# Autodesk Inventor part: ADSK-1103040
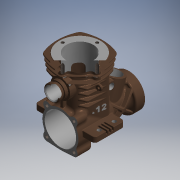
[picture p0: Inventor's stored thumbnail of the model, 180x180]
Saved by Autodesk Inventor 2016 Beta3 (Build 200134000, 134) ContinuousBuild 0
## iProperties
Shininess: 11.0
Compacted: True
Length Units: 11269
Angle Units: 11279
Time Units: 11290
Mass Units: 11286
Length Display Precision: 2
Angle Display Precision: 2
Created: 2000-07
Part Number: ADSK-1103040
Document SubType Name: Modeling
Description: ENGINE  CASE - REAR
Mass: 106.427 g
Surface Area: 158.116 cm^2
Volume: 13.1716 cm^3
Density: 8.08 g/cm^3
Material: Stainless Steel
Appearance: Bronze - Satin
Density: 0.0
Volumn: 0.0
Area: 0.0
PropertySet Name: Model Information
Control State: 0
Master: False
Checked Out: False
Author: Autodesk, Inc.
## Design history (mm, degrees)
node "Extrusion1" dims "d2" = 3.5, "d3" = 0
  sketch "Sketch2"
    geometry: L1 (-28.715, -16.977)-(11.285, -16.977); L2 (11.285, -16.977)-(11.285, 3.023); L3 (11.285, 3.023)-(-28.715, 3.023); L4 (-28.715, 3.023)-(-28.715, -16.977)
    constraints: 8 end point, 2 parallel, 1 horizontal, 1 perpendicular
    dimensions: "d0" = 40 distance of L2.end L3.end; "d1" = 20 distance of L3.end L1.start
workplane "Work Plane1"
workplane "Work Plane2"
node "Extrusion2" dims "d6" = 25.5, "d7" = 0
  sketch "Sketch3"
    geometry: L1 (20, -16.8)-(20, 16.8) reference; L2 (0, 0)-(40, 0) reference; C1 r 12 at (20, 0)
    constraints: 1 centre point, 1 midpoint
    dimensions: "d5" = 24 diameter of C1
node "Extrusion3" dims "d13" = 25, "d14" = 0
  sketch "Sketch4"
    geometry: L1 (-20.715, 3.023)-(3.285, 3.023); L2 (-2.715, -16.977)-(-14.715, -16.977); L3 (-8.715, -21.506)-(-8.715, 7.111) reference; L4 (-28.715, -16.977)-(-20.715, -16.977) reference; A1 r 36.333 centre (-33.049, 3.023) between (-2.715, -16.977) and (3.285, 3.023); A2 r 36.333 centre (15.618, 3.023) between (-20.715, 3.023) and (-14.715, -16.977)
    constraints: 4 end point, 4 point on circle, 2 centre point, 2 point on line, 1 collinear, 1 horizontal
    dimensions: "d8" = 24 distance of L1.start L1.end; "d9" = 12 distance of L2.start L2.end; "d10" = 6 distance from line of L3 L2.start (= 0.5 x d9); "d11" = 12 distance from line of L1.end L3 (= 0.5 x d8); "d12" = 20 distance between parallel lines of L2 L1
node "Extrusion5" dims "d18" = 14, "d19" = 0
  sketch "Sketch6"
    geometry: C1 r 11.33 at (0, 0); C2 r 8 at (0, 0); C3 r 12 at (0, 0) reference
    constraints: 2 centre point, 1 coincident
    dimensions: "d17" = 16 diameter of C2
workplane "Work Plane15"
node "Extrusion6" dims "d21" = 6, "d22" = 0
  sketch "Sketch7"
    geometry: C1 r 7.5 at (0, 0); C2 r 11 at (0, 0)
    constraints: 2 centre point, 1 coincident
    dimensions: "d20" = 22 diameter of C2
fillet "Fillet48" dims "d248" = 2
fillet "Fillet53" dims "d264" = 2, "d265" = 1
feature "LoftSrf2" dims "d266" = 0, "d267" = 90 deg, "d268" = 0, "d269" = 90 deg
  node "Edges3"
  node "Edges4"
feature "OffsetSrf1" dims "d270" = 1, "d271" = 1
node "Revolution1" dims "d28" = 90 deg
  sketch "Sketch10"
    geometry: L1 (-20, -3.5)-(0, -3.5) reference; L2 (-20.351, 1.344)-(-25.14, 14.5); L3 (-25.14, 14.5)-(-31.718, 12.106); L4 (-31.718, 12.106)-(-26.929, -1.05); L5 (-26.929, -1.05)-(-20.351, 1.344); L6 (-22.5, 4.5)-(-36.5, 4.5) reference; L7 (-22.5, -15.5)-(-22.5, 8.5) reference; 1 further point
    constraints: 8 end point, 2 perpendicular, 2 point on line, 1 parallel
    dimensions: "d26" = 70 deg angle of L1 L2; "d27" = 14 diameter of L2 L4; "d231" = 14 distance of L2.start L2.end; "d241" = 10 distance from line of L6 L2.end; "d242" = 1 distance from line of L7 point (-21.5, 4.5)
workplane "Work Plane3"
  workaxis "Work Axis1"
workaxis "Work Axis2"
workplane "Work Plane5"
workplane "Work Plane30"
node "Extrusion12" dims "d54" = 8, "d55" = 0
  sketch "Sketch15"
    geometry: L1 (-9, 9)-(9, 9); L2 (9, 9)-(9, -9); L3 (9, -9)-(-9, -9); L4 (-9, -9)-(-9, 9); C1 r 12 at (0, 0) reference; C2 r 2.5 at (-9, 9); C3 r 2.5 at (9, 9); C4 r 2.5 at (9, -9); C5 r 2.5 at (-9, -9)
    constraints: 8 end point, 4 centre point, 4 coincident, 3 equal radius, 2 parallel, 2 perpendicular, 1 horizontal
    dimensions: "d50" = 18 distance of L2.end L3.end; "d51" = 9 distance from line of C1.centre L4 (= 0.5 x d50); "d52" = 9 distance from line of C1.centre L3 (= d51); "d53" = 5 diameter of C3
node "Extrusion13" dims "d56" = 8, "d57" = 0
  sketch "Sketch16"
    geometry: L1 (10.857, -11.496)-(19.314, -11.98); L2 (29.143, -11.496)-(20.686, -11.98); A1 r 2.5 centre (11, -9) between (10.039, -6.692) and (13.308, -9.961) reference; A2 r 12 centre (20, 0) between (13.308, -9.961) and (26.692, -9.961) reference; A3 r 2.5 centre (29, -9) between (26.692, -9.961) and (29.961, -6.692) reference
    constraints: 4 end point, 4 point on circle, 4 tangent
node "Fillet1" dims "d58" = 2.5
node "Fillet3" dims "d60" = 5
node "Fillet4" dims "d61" = 3
node "Fillet5" dims "d62" = 2
node "Revolution2" dims "d63" = 180 deg
  sketch "Sketch17"
    geometry: L1 (0.686, 11.98)-(9.143, 11.496) reference; L2 (9.143, 11.496)-(0.686, 11.98); L3 (0.686, 11.98)-(0.543, 9.484); L4 (0.543, 9.484)-(9, 9); L5 (9, 9)-(9.143, 11.496); L6 (9, 9)-(11.496, 8.857); A1 r 12 centre (0, 0) between (9.961, 6.692) and (0.686, 11.98) reference; A2 r 2.5 centre (9, 9) between (9.961, 6.692) and (9.143, 11.496) reference
    constraints: 10 end point, 3 equal length, 2 perpendicular, 2 tangent, 1 point on circle, 1 point on line
node "Mirror2"
node "Fillet6" dims "d64" = 2.5
node "Fillet8" dims "d66" = 3.5
node "Fillet17" dims "d75" = 2
node "Fillet18" dims "d76" = 0.3
node "Fillet19" dims "d77" = 0.5
node "Extrusion14" dims "d84" = 9, "d85" = 0
  sketch "Sketch18"
    geometry: L1 (-17.028, 3.023)-(-0.402, 3.023) reference; L2 (-8.715, -25.077)-(-8.715, 10.623) reference; C1 r 10.018 at (-8.715, -6.996); A1 r 36.333 centre (15.618, 3.023) between (-20.508, -0.85) and (-16.281, -14.371) reference
    constraints: 2 tangent, 1 centre point, 1 point on line
node "Extrusion15" dims "d90" = 1, "d91" = 0
  sketch "Sketch19"
    geometry: L1 (5.035, 6.754)-(-22.465, 6.754); L2 (-22.465, 6.754)-(-22.465, -20.746); L3 (-22.465, -20.746)-(5.035, -20.746); L4 (5.035, -20.746)-(5.035, 6.754); A1 r 10.018 centre (-8.715, -6.996) between (0.549, -10.81) and (-8.715, 3.023) reference; A2 r 27.5 centre (-22.465, -6.996) between (2.599, -18.31) and (2.599, 4.319); A3 r 27.5 centre (5.035, -6.996) between (-20.03, 4.319) and (-20.03, -18.31); A4 r 27.5 centre (-8.715, 6.754) between (-20.03, -18.31) and (2.599, -18.31); A5 r 27.5 centre (-8.715, -20.746) between (2.599, 4.319) and (-20.03, 4.319); A6 r 29.032 centre (-8.715, -20.746) between (-22.465, 4.823) and (-23.458, 4.264)
    constraints: 12 point on circle, 8 end point, 5 centre point, 3 midpoint, 3 tangent, 2 parallel, 2 perpendicular, 1 horizontal, 1 point on line
    dimensions: "d86" = 27.5 distance of L2.end L3.end; "d87" = 13.75 distance from line of L4 A1.centre (= 0.5 x d86); "d88" = 13.75 distance from line of L3 A1.centre (= d87); "d89" = 13.75 distance from line of L2 A4.centre (= d87)
node "Fillet26" dims "d92" = 2
workplane "Work Plane6"
node "Extrusion16" dims "d95" = 1, "d96" = 0
  sketch "Sketch20"
    geometry: A1 r 27.5 centre (-8.715, -20.746) between (1.847, 4.645) and (-19.278, 4.645) reference; A2 r 27.5 centre (5.035, -6.996) between (-20.356, 3.567) and (-20.356, -17.558) reference; A3 r 2 centre (-18.509, 2.798) between (-19.278, 4.645) and (-20.356, 3.567) reference; A4 r 2 centre (1.079, 2.798) between (2.925, 3.567) and (1.847, 4.645) reference; A5 r 27.5 centre (-22.465, -6.996) between (2.925, -17.558) and (2.925, 3.567) reference; A6 r 2 centre (1.079, -16.79) between (1.847, -18.636) and (2.925, -17.558) reference; A7 r 27.5 centre (-8.715, 6.754) between (-19.278, -18.636) and (1.847, -18.636) reference; A8 r 2 centre (-18.509, -16.79) between (-20.356, -17.558) and (-19.278, -18.636) reference; A9 r 28 centre (-8.715, -20.746) between (2.039, 5.107) and (-19.47, 5.107); A10 r 2.5 centre (1.079, 2.798) between (3.387, 3.759) and (2.039, 5.107); A11 r 28 centre (-22.465, -6.996) between (3.387, -17.75) and (3.387, 3.759); A12 r 2.5 centre (1.079, -16.79) between (2.039, -19.098) and (3.387, -17.75); A13 r 28 centre (-8.715, 6.754) between (-19.47, -19.098) and (2.039, -19.098); A14 r 2.5 centre (-18.509, -16.79) between (-20.818, -17.75) and (-19.47, -19.098); A15 r 28 centre (5.035, -6.996) between (-20.818, 3.759) and (-20.818, -17.75); A16 r 2.5 centre (-18.509, 2.798) between (-19.47, 5.107) and (-20.818, 3.759)
    constraints: 16 point on circle, 8 centre point, 7 other
    dimensions: "d94" = 0.5 radial gap between concentric circles of A9 A1
workplane "Work Plane7"
node "Extrusion17" dims "d99" = 1, "d100" = 0
  sketch "Sketch21"
    geometry: A1 r 28 centre (-8.715, -20.746) between (2.039, 5.107) and (-19.47, 5.107) reference; A2 r 28 centre (5.035, -6.996) between (-20.818, 3.759) and (-20.818, -17.75) reference; A3 r 2.5 centre (-18.509, -16.79) between (-20.818, -17.75) and (-19.47, -19.098) reference; A4 r 2.5 centre (-18.509, 2.798) between (-19.47, 5.107) and (-20.818, 3.759) reference; A5 r 28 centre (-8.715, 6.754) between (-19.47, -19.098) and (2.039, -19.098) reference; A6 r 2.5 centre (1.079, -16.79) between (2.039, -19.098) and (3.387, -17.75) reference; A7 r 28 centre (-22.465, -6.996) between (3.387, -17.75) and (3.387, 3.759) reference; A8 r 2.5 centre (1.079, 2.798) between (3.387, 3.759) and (2.039, 5.107) reference; A9 r 28.5 centre (-8.715, -20.746) between (2.231, 5.568) and (-19.662, 5.568); A10 r 3 centre (1.079, 2.798) between (3.849, 3.951) and (2.231, 5.568); A11 r 28.5 centre (-22.465, -6.996) between (3.849, -17.942) and (3.849, 3.951); A12 r 3 centre (1.079, -16.79) between (2.231, -19.56) and (3.849, -17.942); A13 r 28.5 centre (-8.715, 6.754) between (-19.662, -19.56) and (2.231, -19.56); A14 r 3 centre (-18.509, -16.79) between (-21.279, -17.942) and (-19.662, -19.56); A15 r 28.5 centre (5.035, -6.996) between (-21.279, 3.951) and (-21.279, -17.942); A16 r 3 centre (-18.509, 2.798) between (-19.662, 5.568) and (-21.279, 3.951)
    constraints: 16 point on circle, 8 centre point, 7 other
    dimensions: "d98" = 0.5 radial gap between concentric circles of A9 A1
workplane "Work Plane8"
node "Extrusion18" dims "d103" = 1, "d104" = 0
  sketch "Sketch22"
    geometry: A1 r 28.5 centre (-8.715, -20.746) between (2.231, 5.568) and (-19.662, 5.568) reference; A2 r 3 centre (-18.509, 2.798) between (-19.662, 5.568) and (-21.279, 3.951) reference; A3 r 28.5 centre (5.035, -6.996) between (-21.279, 3.951) and (-21.279, -17.942) reference; A4 r 3 centre (-18.509, -16.79) between (-21.279, -17.942) and (-19.662, -19.56) reference; A5 r 28.5 centre (-8.715, 6.754) between (-19.662, -19.56) and (2.231, -19.56) reference; A6 r 3 centre (1.079, -16.79) between (2.231, -19.56) and (3.849, -17.942) reference; A7 r 28.5 centre (-22.465, -6.996) between (3.849, -17.942) and (3.849, 3.951) reference; A8 r 3 centre (1.079, 2.798) between (3.849, 3.951) and (2.231, 5.568) reference; A9 r 29 centre (-8.715, -20.746) between (2.423, 6.03) and (-19.854, 6.03); A10 r 3.5 centre (1.079, 2.798) between (4.31, 4.143) and (2.423, 6.03); A11 r 29 centre (-22.465, -6.996) between (4.31, -18.134) and (4.31, 4.143); A12 r 3.5 centre (1.079, -16.79) between (2.423, -20.021) and (4.31, -18.134); A13 r 29 centre (-8.715, 6.754) between (-19.854, -20.021) and (2.423, -20.021); A14 r 3.5 centre (-18.509, -16.79) between (-21.741, -18.134) and (-19.854, -20.021); A15 r 29 centre (5.035, -6.996) between (-21.741, 4.143) and (-21.741, -18.134); A16 r 3.5 centre (-18.509, 2.798) between (-19.854, 6.03) and (-21.741, 4.143)
    constraints: 16 point on circle, 8 centre point, 7 other
    dimensions: "d102" = 0.5 radial gap between concentric circles of A9 A1
node "Extrusion19" dims "d108" = 1, "d109" = 0
  sketch "Sketch23" dims "d105" = 23
    geometry: L1 (-8.715, -31.799)-(-8.715, 35.076) reference; C1 r 10.018 at (-8.715, -6.996) reference; A1 r 2 centre (-8.715, 4.504) between (-6.717, 4.422) and (-10.714, 4.422); A2 r 2 centre (-4.719, 4.339) between (-6.717, 4.422) and (-5.384, 2.453); A3 r 2 centre (-12.712, 4.339) between (-12.047, 2.453) and (-10.714, 4.422); A4 r 10.018 centre (-8.715, -6.996) between (-5.384, 2.453) and (-12.047, 2.453); 1 further point
    constraints: 8 point on circle, 4 centre point, 4 tangent, 2 equal radius, 1 coincident, 1 concentric, 1 point on line, 1 vertical alignment, 2 other
    dimensions: "d106" = 4 diameter of A1; "d107" = 2 radius of A2
workaxis "Work Axis3"
node "Circular Pattern2" dims "d110" = 40, "d112" = 360 deg
node "Fillet27" dims "d113" = 0.3
node "Fillet28" dims "d114" = 0.5
workplane "Work Plane9"
node "Fillet34" dims "d130" = 0.45
sketch "Sketch47"
  geometry: L1 (0, 8.296)-(0, -10.725)
  constraints: 2 end point, 1 vertical
feature "Rib1" sketch "Sketch47" dims "d246" = 2, "d247" = 1
fillet "Fillet49" dims "d249" = 1
fillet "Fillet50" dims "d250" = 1
fillet "Fillet51" dims "d251" = 1
fillet "Fillet52" dims "d252" = 1
workplane "Work Plane17"
split "Split2"
sketch "Sketch51"
  geometry: L1 (-37.441, 3.747)-(-20.441, -10.747); L2 (-37.441, -10.747)-(-20.441, 3.747); L3 (-37.441, 4.569)-(-37.441, 2.926); L4 (-37.441, 2.926)-(-29.905, -3.5); L5 (-29.905, -3.5)-(-37.441, -9.926); L6 (-37.441, -9.926)-(-37.441, -11.569); L7 (-37.441, -11.569)-(-28.941, -4.321); L8 (-28.941, -4.321)-(-20.441, -11.569); L9 (-20.441, -11.569)-(-20.441, -9.926); L10 (-20.441, -9.926)-(-27.978, -3.5); L11 (-27.978, -3.5)-(-20.441, 2.926); L12 (-20.441, 2.926)-(-20.441, 4.569); L13 (-20.441, 4.569)-(-28.941, -2.679); L14 (-28.941, -2.679)-(-37.441, 4.569); L15 (-37.441, -13.502)-(-37.441, 6.502) reference; L16 (-20.441, -14.502)-(-20.441, 7.502) reference; 2 further points
  constraints: 28 end point, 12 collinear, 8 parallel, 6 midpoint, 2 horizontal alignment, 1 vertical
  dimensions: "d272" = 1.25 distance between parallel lines of L14 L4
extrude "Extrusion38" join sketch "Sketch51" stored distance "d273" = 14; taper "d274" = 0 deg
mirror "Mirror3"
fillet "Fillet54" dims "d275" = 1
fillet "Fillet58" dims "d279" = 10
fillet "Fillet55" dims "d276" = 0.3
fillet "Fillet57" dims "d278" = 0.3
node "Hole1" dims "d139" = 2.013, "d140" = 4, "d141" = 2, "d142" = 60 deg, "d143" = 5, "d144" = 118 deg
  sketch "Sketch28"
    geometry: A1 r 2.5 centre (29, 9) between (30.967, 7.457) and (27.457, 10.967) reference; A2 r 2.5 centre (11, 9) between (12.543, 10.967) and (9.033, 7.457) reference; A3 r 2.5 centre (11, -9) between (8.939, -7.585) and (10.857, -11.496) reference; A4 r 2.5 centre (29, -9) between (29.143, -11.496) and (31.061, -7.585) reference
node "Extrusion24" dims "d152" = 25, "d153" = 0
  sketch "Sketch30"
    geometry: C1 r 9 at (-8.715, -6.996); A1 r 10.518 centre (-8.715, -6.996) between (-18.635, -10.493) and (-12.213, -16.915) reference
    constraints: 1 centre point, 1 coincident
    dimensions: "d151" = 18 diameter of C1
node "Extrusion25" dims "d154" = 0.25, "d155" = 0
  sketch "Sketch31"
    geometry: C1 r 9 at (-8.715, -6.996) reference; A1 r 28.7 centre (-8.715, 6.754) between (-19.739, -19.744) and (2.308, -19.744) reference; 1 further point
    constraints: 1 coincident, 1 vertical alignment, 2 other
workaxis "Work Axis8"
workplane "Work Plane33"
node "Fillet38" dims "d156" = 0.5
node "Hole3" dims "d157" = 2.013, "d158" = 4, "d159" = 2, "d160" = 60 deg, "d161" = 8, "d162" = 118 deg
  sketch "Sketch32"
    geometry: A1 r 2.5 centre (-8.715, 4.504) between (-6.218, 4.401) and (-11.213, 4.401) reference; 2 further points
node "Circular Pattern3" dims "d163" = 40, "d165" = 360 deg
workplane "Work Plane10"
node "Extrusion26" dims "d172" = 1, "d173" = 0
  sketch "Sketch33"
    geometry: L1 (20.526, -0.599)-(20.124, -12.117); L2 (18.879, -14.443)-(13.845, -16.58); L3 (15.656, -15.268)-(18.907, -13.888); L4 (0.402, 3.023)-(17.028, 3.023) reference; A1 r 36.333 centre (-15.618, 3.023) between (16.281, -14.371) and (20.508, -0.85) reference; A2 r 3.5 centre (17.028, -0.477) between (20.508, -0.85) and (17.028, 3.023) reference; A3 r 5 centre (11.892, -11.977) between (11.892, -16.977) and (16.281, -14.371) reference; A4 r 2 centre (18.125, -12.047) between (18.907, -13.888) and (20.124, -12.117)
    constraints: 6 end point, 5 point on circle, 4 tangent, 1 centre point, 1 parallel
    dimensions: "d168" = 115 deg angle of L2 L1; "d170" = 2 radius of A4; "d171" = 0.5 distance between parallel lines of L2 L3; "d280" = 88 deg angle of L4 L1
node "Fillet39" dims "d174" = 0.3
mirror "Mirror4"
fillet "Fillet59" dims "d281" = 0.5
node "Rectangular Pattern1" dims "d176" = 40, "d178" = 3.5
node "Extrusion27" dims "d180" = 4, "d181" = 0
  sketch "Sketch34"
    geometry: C1 r 11 at (0, 0); C2 r 8 at (0, 0); A1 r 11 centre (0, 0) between (-11, 0) and (11, 0) reference; A2 r 11 centre (0, 0) between (11, 0) and (-11, 0) reference
    constraints: 2 centre point, 1 coincident
    dimensions: "d179" = 16 diameter of C2
node "Extrusion28" dims "d183" = 4, "d184" = 0
  sketch "Sketch35"
    geometry: C1 r 8 at (0, 0) reference; C2 r 6 at (0, 0)
    constraints: 1 centre point, 1 coincident
    dimensions: "d182" = 12 diameter of C2
node "Extrusion29" dims "d186" = 20, "d187" = 0
  sketch "Sketch36"
    geometry: C1 r 10.5 at (20, 0); A1 r 12 centre (20, 0) between (30.859, -5.106) and (30.749, 5.334) reference
    constraints: 1 centre point, 1 coincident
    dimensions: "d185" = 21 diameter of C1
node "Extrusion30" dims "d189" = 22, "d190" = 0
  sketch "Sketch37"
    geometry: C1 r 7 at (-8.715, -6.996); A1 r 13.75 centre (-8.715, -6.996) between (5.035, -6.996) and (-22.465, -6.996) reference
    constraints: 1 centre point, 1 coincident
    dimensions: "d188" = 14 diameter of C1
sketch "Sketch43"
  geometry: L1 (12.324, 33.859)-(-10.939, -30.056); L2 (1.197, 3.289)-(-5.381, 5.683); L3 (-4.342, 9.03)-(5.376, 5.493); L4 (17.596, 48.345)-(-18.614, -51.141) reference; L5 (-8.665, 10.603)-(-8.323, 10.479) reference; L6 (-8.323, 10.479)-(-4.885, 9.227) reference; L7 (-3.975, 8.896)-(-4.885, 9.227) reference; L8 (-3.975, 8.896)-(-3.975, 8.896) reference; L9 (-4.885, 9.227)-(-3.975, 8.896) reference; L10 (-4.885, 9.227)-(-8.323, 10.479) reference; L11 (-8.665, 10.603)-(-8.323, 10.479) reference; C1 r 2.75 at (-5.381, 5.683)
  constraints: 6 end point, 2 collinear, 1 centre point, 1 coincident, 1 perpendicular, 1 point on line
  dimensions: "d216" = 7 distance of L2.start L2.end; "d217" = 3.5 distance between parallel lines of L2 L3; "d218" = 5.5 diameter of C1
extrude "Extrusion39" join sketch "Sketch43" distance "d282" = 14; taper "d283" = 0 deg
fillet "Fillet60" dims "d284" = 0.5
node "Extrusion35" dims "d223" = 15, "d224" = 0
  sketch "Sketch44"
    geometry: C1 r 5.5 at (0, 0); A1 r 7 centre (0, 0) between (1.75, -6.778) and (-1.75, -6.778) reference
    constraints: 1 centre point, 1 concentric
    dimensions: "d222" = 11 diameter of C1
node "Extrusion36" dims "d226" = 15, "d227" = 0
  sketch "Sketch45"
    geometry: C1 r 2.75 at (0, 0); C2 r 2 at (0, 0); C3 r 2.75 at (0, 0) reference
    constraints: 2 centre point, 1 coincident
    dimensions: "d225" = 4 diameter of C2
node "Chamfer1" dims "d228" = 0.5, "d229" = 0.5, "d239" = 45 deg
node "Hole4" dims "d233" = 2.5, "d234" = 4, "d235" = 2, "d236" = 60 deg, "d237" = 8, "d238" = 118 deg
  sketch "Sketch46"
    geometry: C1 r 1.078 at (8.285, -11.027) reference; C2 r 1.078 at (8.285, -1.027) reference; C3 r 1.078 at (-25.715, -1.977) reference; C4 r 1.078 at (-25.715, -11.977) reference
sketch "Sketch52"
  geometry: L1 (1.337, 11.656)-(8.684, 11.656); L2 (8.684, 11.656)-(8.684, 8.517); L3 (8.684, 8.517)-(1.337, 8.517); L4 (1.337, 8.517)-(1.337, 11.656)
  constraints: 2 other
emboss "Emboss1" sketch "Sketch52" dims "d288" = 0.333, "d289" = 0
sketch "Sketch53"
  geometry: L1 (-11.887, 5.713)-(-11.887, 13.872); L2 (-11.887, 13.872)-(-8.327, 13.872); L3 (-8.327, 13.872)-(-8.327, 5.713); L4 (-8.327, 5.713)-(-11.887, 5.713)
  constraints: 2 other
emboss "Emboss2" sketch "Sketch53" dims "d293" = 0.33, "d294" = 0
fillet "Fillet77" dims "d396" = 0.25
fillet "Fillet78" dims "d397" = 0.1
fillet "Fillet79" dims "d398" = 0.25
fillet "Fillet80" dims "d399" = 0.1
split "Split4"
split "Split7"
sketch "Sketch54"
  geometry: L1 (-37.441, -13.502)-(-20.441, -14.502) reference; L2 (-34.186, -13.693)-(-24.164, -14.283); L3 (11.1, -3.5)-(-45.6, -3.5) reference; A1 r 1 centre (-37.5, -13.5) between (-37.5, -14.5) and (-36.5, -13.5) reference; A2 r 2 centre (-20.5, -13.5) between (-22.5, -13.5) and (-20.5, -15.5) reference; A3 r 1 centre (-37.5, -13.5) between (-37.5, -14.5) and (-36.997, -14.364); A4 r 2 centre (-20.5, -13.5) between (-21.631, -15.15) and (-20.5, -15.5); A5 r 5 centre (-34.48, -18.685) between (-34.186, -13.693) and (-36.997, -14.364); A6 r 5 centre (-24.457, -19.274) between (-21.631, -15.15) and (-24.164, -14.283)
  constraints: 10 point on circle, 5 tangent, 4 centre point, 3 equal radius, 2 end point, 1 collinear, 1 point on line
  dimensions: "d295" = 5 radius of A5
feature "RevolutionSrf1" sketch "Sketch54" dims angle "d328" = 10 deg
thicken "Thicken1" dims "d329" = 3, "d330" = 4
node "Extrusion31" dims "d192" = 5, "d193" = 0
  sketch "Sketch38"
    geometry: C1 r 10.5 at (0, 0) reference; C2 r 9.5 at (0, 0)
    constraints: 1 centre point, 1 coincident
    dimensions: "d191" = 19 diameter of C2
fillet "Fillet64" dims "d331" = 0.5
fillet "Fillet65" dims "d332" = 0.5
workplane "Work Plane29"
workplane "Work Plane31"
workaxis "Work Axis7"
sketch "Sketch55"
  geometry: C1 r 6.5 at (0, 23.5); 1 further point
  constraints: 1 centre point, 1 coincident
  dimensions: "d336" = 13 diameter of C1
extrude "Extrusion40" join sketch "Sketch55" stored distance "d337" = 10; taper "d338" = 0 deg
sketch "Sketch57"
  geometry: L1 (2.25, 9.25)-(2.25, 8.75); L2 (3, 1.834)-(3, -8.606) reference; L3 (3, 8.5)-(2, 8.5) reference
  constraints: 2 end point, 1 vertical
  dimensions: "d389" = 0.75 distance between parallel lines of L2 L1; "d390" = 0.25 distance from line of L3 L1.end; "d391" = 0.5 distance of L1.start L1.end
feature "Rib5" sketch "Sketch57" dims "d341" = 1, "d342" = 2
fillet "Fillet66" dims "d343" = 0.5
fillet "Fillet67" dims "d394" = 0.4
fillet "Fillet68" dims "d347" = 0.5
sketch "Sketch58"
  geometry: C1 r 6.5 at (0, 0) reference; C2 r 5.25 at (0, 0); C3 r 7.516 at (0, 0); 2 further points
  constraints: 2 centre point, 2 coincident, 1 horizontal alignment
  dimensions: "d348" = 1.25 radial gap between concentric circles of C2 C1
extrude "Extrusion41" cut sketch "Sketch58" distance "d349" = 6 (derived); taper "d350" = 0 deg
hole "Hole5" diameter "d353" = 8; stored, may be unused: countersink angle "d357" = 90 deg, drill point angle "d359" = 118 deg; dims "d351" = 10, "d352" = 10, "d354" = 6, "d355" = 4, "d356" = 2, "d358" = 8
chamfer "Chamfer2" distance "d360" = 0.5; stored, may be unused: second distance "d361" = 2, angle "d362" = 45 deg
fillet "Fillet76" dims "d393" = 0.5
sketch "Sketch59"
  geometry: L1 (12.125, 12.4)-(12.125, 12.5); L2 (15.875, 12.5)-(15.875, 12.4); A1 r 1.875 centre (14, 12.5) between (15.875, 12.5) and (12.125, 12.5); 1 further point
  constraints: 4 end point, 2 parallel, 2 point on circle, 2 tangent, 1 centre point, 1 vertical, 1 vertical alignment
  dimensions: "d364" = 1.875 radius of A1; "d365" = 12.5 distance of point (14, 0) A1.centre; "d366" = 0.1 distance of L1.start L1.end
extrude "Extrusion42" join sketch "Sketch59" distance "d368" = 1.5; taper "d369" = 0 deg
hole "Hole6" diameter "d372" = 1.5; stored, may be unused: countersink angle "d376" = 90 deg, drill point angle "d378" = 118 deg; dims "d370" = 10, "d371" = 10, "d373" = 6, "d374" = 4, "d375" = 2, "d377" = 8
fillet "Fillet69" dims "d379" = 0.5
mirror "Mirror5"
fillet "Fillet70" dims "d380" = 0.5
fillet "Fillet71" dims "d381" = 0.3
workplane "Work Plane34"
sketch "Sketch60"
  geometry: L1 (11.964, 9.428)-(11.964, 10.362); L2 (11.964, 10.362)-(29.739, 10.362); L3 (-10.2, 0)-(59.45, 0) reference
  constraints: 4 end point, 1 parallel, 1 perpendicular, 1 vertical
revolve "Revolution3" sketch "Sketch60" stored, may be unused: angle "d384" = 45 deg
fillet "Fillet72" dims "d385" = 2
fillet "Fillet73" dims "d386" = 1
mirror "Mirror6"
fillet "Fillet74" dims "d387" = 2
fillet "Fillet75" dims "d388" = 1
sketch "Sketch61" dims "d405" = 10
  geometry: L1 (3.2, 16)-(3.2, 0) reference; L2 (3.5, 10.482)-(1.5, 10.482); L3 (1.5, 10.482)-(1.5, 9.482); L4 (1.5, 9.482)-(3.5, 9.482); L5 (3.5, 9.482)-(3.5, 10.482); L6 (3.5, 8.482)-(1.5, 8.482); L7 (1.5, 8.482)-(1.5, 7.482); L8 (1.5, 7.482)-(3.5, 7.482); L9 (3.5, 7.482)-(3.5, 8.482); L10 (3.5, 6.482)-(1.5, 6.482); L11 (1.5, 6.482)-(1.5, 5.482); L12 (1.5, 5.482)-(3.5, 5.482); L13 (3.5, 5.482)-(3.5, 6.482); L14 (47.7, 7.982)-(-21.95, 7.982) reference; L15 (3.5, 0)-(3.5, 16) reference
  constraints: 24 end point, 6 parallel, 3 perpendicular, 1 collinear, 1 horizontal, 1 vertical, 17 other
  dimensions: "d402" = 2 distance of L2.start L6.start; "d407" = 1 distance of L4.end L2.start; "d408" = 2 distance of L2.start L2.end
extrude "Extrusion43" cut sketch "Sketch61" distance "d409" = 6; taper "d410" = 0 deg
fillet "Fillet81" dims "d411" = 0.5
mirror "Mirror7"
sketch "Sketch62"
  geometry: L1 (8.5, 25.25)-(3, 25.25) reference; L2 (3, 23.411)-(3, 13.5) reference; L3 (5, 25.25)-(6.5, 25.25); L4 (6.5, 25.25)-(6.5, 24.5); L5 (6.5, 24.5)-(5, 24.5); L6 (5, 24.5)-(5, 25.25); L7 (9, 24.75)-(9, 15.25) reference; L8 (9, 20)-(8.345, 20)
  constraints: 10 end point, 2 parallel, 2 perpendicular, 1 horizontal, 1 midpoint, 1 point on line
  dimensions: "d422" = 0.75 distance of L3.end L4.end; "d423" = 1.5 distance between parallel lines of L4 L6; "d424" = 2.5 distance between parallel lines of L7 L4
revolve "Revolution4" sketch "Sketch62" stored, may be unused: angle "d425" = 90 deg
workplane "Work Plane35"
body "Solid1"
body "Srf1"
body "Srf2"
node "Projected Loop1"
body "Srf3"
other parameters: "d4" = 3, "d37" = 45 deg, "d93" = 2, "d97" = 2, "d101" = 2, "d115" = -15, "d166" = 2, "d240" = 14, "d259" = 0, "d333" = 9, "d334" = 0, "d335" = 23.5, "d345" = 0, "d367" = 1.5, "d383" = 30 deg, "d418" = 40 deg, "d421" = 0
